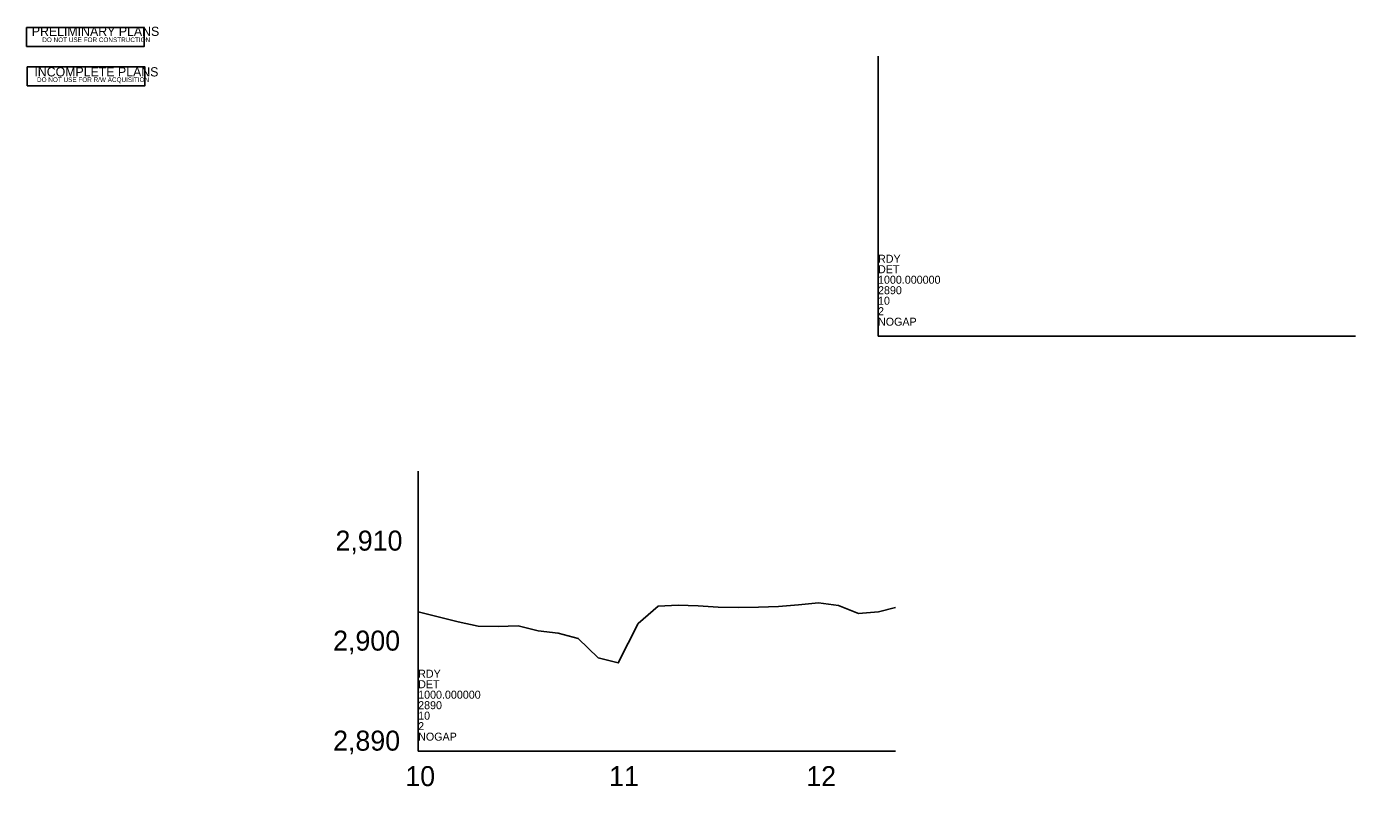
# Model space of a CAD drawing. Extents: x 1191114 to 1192543, y 893004 to 894332.
# Drawn here: x 1191879 to 1192543, y 893938 to 894318 of the extents above; entities that cross this region are included whole.
import ezdxf

# ---------------------------------------------------------------- set-up
doc = ezdxf.new("R2010")
doc.units = 0
for name, color, linetype in [('Exist Profile Cell', 7, 'Continuous'), ('Exist Vertical Profile Ground Line', 7, 'Continuous'), ('Exist Vertical Profile Horizontal Axis Label Major', 7, 'Continuous'), ('Exist Vertical Profile Vertical Axis Label', 7, 'Continuous'), ('Sheet Sticker Incomplete CELL', 7, 'Continuous'), ('Sheet Sticker Preliminary CELL', 7, 'Continuous')]:
    doc.layers.add(name, color=color, linetype=linetype)

msp = doc.modelspace()

# ---------------------------------------------------------------- linework, layer by layer
at = {"layer": 'Exist Profile Cell'}
for p, q in [((1192304.77, 894163.39), (1192304.77, 894303.39)), ((1192304.77, 894163.39), (1192543.35, 894163.39)), ((1192304.77, 894163.39), (1192304.77, 894163.39)), ((1192074.96, 893955.93), (1192074.96, 894095.93)), ((1192074.96, 893955.93), (1192313.54, 893955.93)), ((1192074.96, 893955.93), (1192074.96, 893955.93))]:
    msp.add_line(p, q, dxfattribs=at)
at = {"layer": 'Exist Vertical Profile Ground Line'}
msp.add_lwpolyline([(1192074.96, 894025.66), (1192084.96, 894023.07), (1192094.96, 894020.63), (1192104.96, 894018.36), (1192114.96, 894018.25), (1192124.96, 894018.54), (1192134.96, 894016.12), (1192144.96, 894014.97), (1192154.96, 894012.17), (1192164.96, 894002.52), (1192174.96, 894000.08), (1192184.96, 894019.7), (1192194.96, 894028.36), (1192204.96, 894028.88), (1192214.96, 894028.53), (1192224.96, 894027.98), (1192234.96, 894027.7), (1192244.96, 894027.97), (1192254.96, 894028.32), (1192264.96, 894029.16), (1192274.96, 894030.13), (1192284.96, 894028.78), (1192294.96, 894024.71), (1192304.96, 894025.58), (1192313.54, 894027.75)], dxfattribs=at)
at = {"layer": 'Sheet Sticker Incomplete CELL'}
msp.add_lwpolyline([(1191879.59, 894288.57), (1191879.59, 894297.97), (1191938.39, 894297.97), (1191938.39, 894288.57)], close=True, dxfattribs=at)
at = {"layer": 'Sheet Sticker Preliminary CELL'}
msp.add_lwpolyline([(1191879.27, 894308.24), (1191879.27, 894317.64), (1191938.07, 894317.64), (1191938.07, 894308.24)], close=True, dxfattribs=at)

# ---------------------------------------------------------------- texts
at = {"layer": 'Exist Profile Cell'}
for s, p in [('RDY', (1192304.77, 894200.1)), ('DET', (1192304.77, 894194.85)), ('1000.000000', (1192304.77, 894189.61)), ('2890', (1192304.77, 894184.37)), ('10', (1192304.77, 894179.12)), ('2', (1192304.77, 894173.88)), ('NOGAP', (1192304.77, 894168.63)), ('RDY', (1192074.96, 893992.64)), ('DET', (1192074.96, 893987.39)), ('1000.000000', (1192074.96, 893982.15)), ('2890', (1192074.96, 893976.9)), ('10', (1192074.96, 893971.66)), ('2', (1192074.96, 893966.42)), ('NOGAP', (1192074.96, 893961.17))]:
    msp.add_text(s, height=4, dxfattribs=at).set_placement(p)
at = {"layer": 'Exist Vertical Profile Horizontal Axis Label Major'}
for s, p in [('10', (1192068.54, 893938.43)), ('11', (1192170.38, 893938.43)), ('12', (1192268.93, 893938.43))]:
    msp.add_text(s, height=10, dxfattribs=at).set_placement(p)
at = {"layer": 'Exist Vertical Profile Vertical Axis Label'}
for s, p in [('2,910', (1192033.65, 894056.18)), ('2,900', (1192032.46, 894006.18)), ('2,890', (1192032.46, 893956.18))]:
    msp.add_text(s, height=10, dxfattribs=at).set_placement(p)
at = {"layer": 'Sheet Sticker Incomplete CELL'}
for s, height, p in [('INCOMPLETE PLANS', 4.608, (1191883.17, 894293.25)), ('DO NOT USE FOR R/W ACQUISITION', 2.304, (1191884.47, 894290.47))]:
    msp.add_text(s, height=height, dxfattribs=at).set_placement(p)
at = {"layer": 'Sheet Sticker Preliminary CELL'}
for s, height, p in [('PRELIMINARY PLANS', 4.608, (1191881.87, 894313.5)), ('DO NOT USE FOR CONSTRUCTION', 2.304, (1191887.11, 894310.42))]:
    msp.add_text(s, height=height, dxfattribs=at).set_placement(p)

doc.saveas('drawing.dxf')
